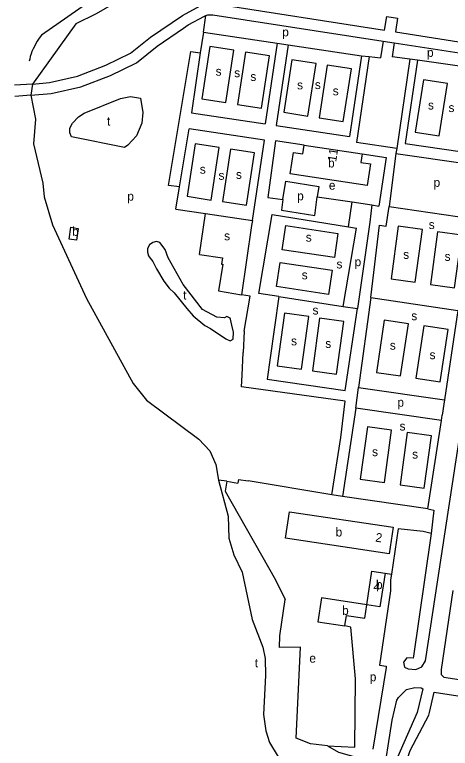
# Model space of a CAD drawing. Extents: x 161093 to 163177, y 379000 to 380904.
# Drawn here: x 161129 to 161325.1, y 380148.5 to 380478.7 of the extents above; entities that cross this region are included whole.
import ezdxf

# ---------------------------------------------------------------- set-up
doc = ezdxf.new("R2010")
doc.units = 0
for name, color, linetype in [('BLT_Basislijn', 7, 'Continuous'), ('BLT_Bebouwing', 7, 'Continuous'), ('BLT_Centroide', 7, 'Continuous'), ('BLT_Huisnummer', 7, 'Continuous'), ('BLT_Vlakafsluiter', 7, 'Continuous')]:
    doc.layers.add(name, color=color, linetype=linetype)

msp = doc.modelspace()

# ---------------------------------------------------------------- linework, layer by layer
at = {"layer": 'BLT_Basislijn'}
for p, q in [((161164.87, 380486.08), (161141.11, 380469.52)), ((161213.97, 380470.87), (161215.05, 380478.25)), ((161213.97, 380470.87), (161212.59, 380461.47)), ((161213.97, 380470.87), (161247.21, 380465.91)), ((161247.21, 380465.91), (161241.82, 380429.61)), ((161252.14, 380465.09), (161246.75, 380428.79)), ((161247.21, 380465.91), (161252.14, 380465.09)), ((161252.14, 380465.09), (161285.1, 380460.17)), ((161294.86, 380466.8), (161293.76, 380459.24)), ((161294.86, 380466.8), (161299.8, 380466.04)), ((161299.8, 380466.04), (161298.88, 380459.75)), ((161299.8, 380466.04), (161333.35, 380460.86)), ((161212.59, 380461.47), (161208.62, 380434.57)), ((161285.1, 380460.17), (161279.71, 380423.86)), ((161288.55, 380459.85), (161282.85, 380421.09)), ((161285.1, 380460.17), (161288.55, 380459.85)), ((161288.55, 380459.85), (161293.76, 380459.24)), ((161306.83, 380458.65), (161298.88, 380459.75)), ((161306.83, 380458.65), (161300.97, 380418.43)), ((161332.45, 380455.09), (161310.37, 380458.16)), ((161137.07, 380447.48), (161129.03, 380446.89)), ((161319.48, 380224.32), (161352.93, 380444.22)), ((161136.28, 380442.39), (161129.11, 380441.88)), ((161136.28, 380442.39), (161138.38, 380431.69)), ((161160.25, 380434.41), (161176.64, 380440.92)), ((161208.62, 380434.57), (161241.82, 380429.61)), ((161246.75, 380428.79), (161279.71, 380423.86)), ((161203.26, 380401.14), (161207.6, 380427.32)), ((161300.97, 380418.43), (161282.85, 380421.09)), ((161300.97, 380418.43), (161300.65, 380416.24)), ((161300.65, 380416.24), (161297.61, 380392.33)), ((161300.65, 380416.24), (161338.09, 380410.75)), ((161201.62, 380391.21), (161203.26, 380401.14)), ((161280.87, 380394.42), (161289.73, 380393.05)), ((161201.62, 380391.21), (161214.99, 380389.19)), ((161289.73, 380393.05), (161292.92, 380392.55)), ((161212.23, 380370.74), (161214.99, 380389.19)), ((161214.99, 380389.19), (161236.01, 380386)), ((161276.92, 380347.43), (161282.88, 380382.65)), ((161279.27, 380383.23), (161282.88, 380382.65)), ((161289.31, 380351.48), (161283.84, 380310.9)), ((161289.31, 380351.48), (161328.55, 380345.63)), ((161276.92, 380347.43), (161283.27, 380346.46)), ((161328.55, 380345.63), (161322.52, 380305.29)), ((161295.41, 380341.22), (161291.82, 380317.68)), ((161313.19, 380338.61), (161309.64, 380315.11)), ((161231.43, 380316.44), (161231.92, 380326.6)), ((161309.64, 380315.11), (161320.54, 380313.53)), ((161282.53, 380301.57), (161283.84, 380310.9)), ((161322.52, 380305.29), (161322.25, 380303.47)), ((161322.25, 380303.47), (161321.44, 380298.45)), ((161314.99, 380256.29), (161321.08, 380296.09)), ((161321.08, 380296.09), (161321.44, 380298.45)), ((161229.79, 380269.57), (161234.13, 380268.9)), ((161271.81, 380262.66), (161234.13, 380268.9)), ((161224.57, 380268.68), (161229.51, 380267.86)), ((161276.56, 380261.87), (161271.81, 380262.66)), ((161314.99, 380256.29), (161276.56, 380261.87)), ((161316.48, 380245.23), (161313.46, 380224.32)), ((161295.83, 380227.34), (161298.65, 380226.92)), ((161298.65, 380226.92), (161298.26, 380224.32)), ((161246.49, 380224.32), (161250.75, 380215.57))]:
    msp.add_line(p, q, dxfattribs=at)
for points in [[(161184.65, 380498.1), (161178.49, 380486.62), (161165.7, 380479.06), (161156.61, 380474.6), (161137.07, 380447.48)], [(161213.84, 380483.12), (161215.09, 380483.55), (161218.52, 380483.64), (161295.56, 380471.7), (161296.49, 380477.82), (161301.35, 380477.09), (161300.47, 380470.93), (161328.98, 380466.5), (161329.9, 380472.69), (161334.48, 380471.98), (161335.13, 380471.86), (161352.54, 380469.32), (161354.21, 380468.64), (161355.48, 380467.36), (161355.94, 380465.82), (161356, 380464.58), (161355.58, 380461.89)], [(161137.07, 380447.48), (161144.71, 380448.17), (161157.32, 380451.01), (161170.13, 380455.89), (161181.11, 380461.31), (161190.23, 380468.57), (161204.57, 380478.35), (161212.5, 380482.66), (161213.84, 380483.12)], [(161204.95, 380472.56), (161207.18, 380474.08), (161214.51, 380478.06), (161215.05, 380478.25)], [(161215.05, 380478.25), (161215.98, 380478.57), (161218.2, 380478.63), (161294.86, 380466.8)], [(161136.28, 380442.39), (161145.49, 380443.22), (161158.76, 380446.21), (161172.13, 380451.3), (161183.8, 380457.06), (161193.2, 380464.55), (161204.95, 380472.56)], [(161141.11, 380469.52), (161140.05, 380468.16), (161139.18, 380466.72), (161138.61, 380465.64), (161137.9, 380464.32), (161137.33, 380463.25), (161136.83, 380462.14), (161136.4, 380461), (161136.06, 380459.84), (161135.79, 380458.66), (161135.63, 380457.76)], [(161216.87, 380464.36), (161213.22, 380440.78), (161224.06, 380439.1), (161227.71, 380462.68), (161216.87, 380464.36)], [(161203.26, 380401.14), (161198.32, 380401.88), (161208.3, 380462.17), (161212.59, 380461.47)], [(161232.91, 380461.81), (161229.26, 380438.22), (161240.1, 380436.55), (161243.75, 380460.13), (161232.91, 380461.81)], [(161253.84, 380458.33), (161250.19, 380434.75), (161261.03, 380433.07), (161264.68, 380456.65), (161253.84, 380458.33)], [(161310.37, 380458.16), (161304.76, 380420.69), (161338.82, 380415.69)], [(161310.37, 380458.16), (161306.83, 380458.65)], [(161269.74, 380455.92), (161266.09, 380432.33), (161276.93, 380430.66), (161280.58, 380454.24), (161269.74, 380455.92)], [(161312.97, 380449.36), (161309.31, 380425.78), (161320.15, 380424.1), (161323.8, 380447.69), (161312.97, 380449.36)], [(161176.64, 380440.92), (161181.15, 380441.89), (161185.62, 380441.13), (161186.65, 380434.59), (161186.33, 380429.93), (161183.86, 380424.16), (161179.94, 380420.01), (161178.45, 380418.98), (161154.54, 380423.68), (161153.86, 380425.44), (161153.86, 380427.63), (161155.11, 380429.82), (161157.71, 380432.68), (161160.25, 380434.41)], [(161138.38, 380431.69), (161137.56, 380420.54), (161141.7, 380402.83), (161142.3, 380396.73), (161146.06, 380384.11), (161161.38, 380350.9), (161182.43, 380312.66), (161188.42, 380305.19), (161211.96, 380287.61), (161216.94, 380282.42), (161219.64, 380276.21), (161220.85, 380269.22)], [(161236.01, 380386), (161241.49, 380422.18), (161207.6, 380427.32)], [(161259.33, 380419.95), (161246.45, 380421.9), (161242.93, 380396.36), (161249.74, 380395.45)], [(161210.3, 380420.54), (161206.64, 380396.96), (161217.48, 380395.28), (161221.13, 380418.86), (161210.3, 380420.54)], [(161226.2, 380418.2), (161222.54, 380394.62), (161233.38, 380392.94), (161237.03, 380416.52), (161226.2, 380418.2)], [(161285.47, 380416.02), (161296.22, 380414.37), (161292.92, 380392.55)], [(161249.74, 380395.45), (161251.02, 380403.74), (161265.9, 380401.35), (161265.2, 380396.75)], [(161249.74, 380395.45), (161249.42, 380393.07), (161249.07, 380390.76), (161264.06, 380388.38), (161264.4, 380390.7), (161265.2, 380396.75)], [(161265.2, 380396.75), (161280.87, 380394.42)], [(161279.27, 380383.23), (161280.87, 380394.42)], [(161289.73, 380393.05), (161288.85, 380385.33), (161283.27, 380346.46)], [(161289.31, 380351.48), (161293.3, 380383.97), (161296.23, 380383.56), (161297.61, 380392.33)], [(161297.61, 380392.33), (161334.56, 380386.89)], [(161247.99, 380351.85), (161239, 380353.24), (161244.9, 380388.8), (161279.27, 380383.23)], [(161236.01, 380386), (161235.7, 380383.77), (161231.15, 380352.64)], [(161251.11, 380383.75), (161274.55, 380380.22), (161272.92, 380369.38), (161249.47, 380372.9), (161251.11, 380383.75)], [(161301.66, 380383.52), (161298.42, 380359.87), (161309.29, 380358.38), (161312.53, 380382.03), (161301.66, 380383.52)], [(161319.38, 380380.94), (161316.14, 380357.3), (161327, 380355.81), (161330.24, 380379.45), (161319.38, 380380.94)], [(161212.23, 380370.74), (161222.58, 380369.24), (161222.15, 380366.47), (161222.71, 380366.38), (161220.81, 380354.34), (161231.15, 380352.64)], [(161248.5, 380367.17), (161271.94, 380363.64), (161270.31, 380352.8), (161246.87, 380356.32), (161248.5, 380367.17)], [(161232.38, 380336.33), (161235.02, 380352), (161231.15, 380352.64)], [(161247.99, 380351.85), (161244.02, 380324.3), (161242.65, 380314.65)], [(161247.99, 380351.85), (161276.92, 380347.43)], [(161242.65, 380314.65), (161277.86, 380309.62), (161283.27, 380346.46)], [(161250.49, 380344.36), (161247.25, 380320.71), (161258.12, 380319.22), (161261.36, 380342.87), (161250.49, 380344.36)], [(161266.29, 380342.04), (161263.05, 380318.39), (161273.92, 380316.9), (161277.16, 380340.55), (161266.29, 380342.04)], [(161291.82, 380317.68), (161302.74, 380316.11), (161306.32, 380339.62), (161295.41, 380341.22)], [(161320.54, 380313.53), (161324.1, 380337.03), (161313.19, 380338.61)], [(161232.38, 380336.33), (161231.92, 380326.6)], [(161231.16, 380311.14), (161231.43, 380316.44)], [(161271.81, 380262.66), (161275.84, 380288.37), (161277.77, 380304.68), (161231.16, 380311.14)], [(161283.84, 380310.9), (161322.52, 380305.29)], [(161282.53, 380301.57), (161276.56, 380261.87)], [(161321.08, 380296.09), (161282.53, 380301.57)], [(161287.84, 380293.26), (161284.6, 380269.62), (161295.46, 380268.13), (161298.7, 380291.77), (161287.84, 380293.26)], [(161305.76, 380290.7), (161302.52, 380267.06), (161313.38, 380265.57), (161316.62, 380289.21), (161305.76, 380290.7)], [(161220.85, 380269.22), (161225.11, 380253.05), (161225.4, 380243.06)], [(161229.79, 380269.57), (161229.51, 380267.86)], [(161224.57, 380268.68), (161223.84, 380264.27), (161246.49, 380224.32)], [(161314.99, 380256.29), (161317.7, 380255.64), (161316.48, 380245.23)], [(161316.48, 380245.23), (161312.96, 380246.05), (161301.69, 380247.32), (161298.65, 380226.92)], [(161225.4, 380243.06), (161227.67, 380235.59), (161231.49, 380227.73), (161235.88, 380206.53), (161240.79, 380193.99), (161241.73, 380188.94), (161241.93, 380181.27), (161241.02, 380163.69), (161242.04, 380156.47), (161243.72, 380151.15), (161247.7, 380144.74)], [(161298.26, 380224.32), (161298.18, 380219.44), (161293.21, 380186), (161296.19, 380185.57), (161296.27, 380184.85), (161290.29, 380148.22)], [(161313.46, 380224.32), (161308.51, 380189.99), (161308.32, 380189.17), (161305.55, 380189.2), (161304.05, 380187.29), (161304.56, 380185.04), (161306.17, 380184.29), (161309.62, 380183.97), (161312.27, 380185.22), (161313.92, 380187.83), (161319.48, 380224.32)], [(161326.24, 380219.49), (161320.93, 380184.07), (161320.96, 380181.79), (161322.14, 380180.53), (161384, 380171.06), (161385.05, 380170.9)], [(161257.64, 380194.04), (161248.24, 380193.93), (161248.31, 380199.15), (161250.75, 380215.57)], [(161269.88, 380149.64), (161282.17, 380149.06), (161282.5, 380179.86), (161280.41, 380203.1), (161277.65, 380203.6)], [(161269.88, 380149.64), (161262.16, 380150.59), (161255.78, 380153.11), (161257.64, 380194.04)], [(161294.65, 380133.35), (161298.9, 380161.26), (161301.02, 380170.18), (161301.82, 380171.41), (161305.42, 380174.93), (161309.08, 380175.9), (161312.06, 380175.79), (161312.69, 380175.36), (161310.26, 380164.67), (161299.91, 380141.03)], [(161315.69, 380164.58), (161317.84, 380173.75), (161342.15, 380170.09)], [(161305.97, 380120.42), (161304.44, 380133.57), (161304.88, 380139.67), (161305.64, 380143.48), (161307.07, 380147.62), (161315.45, 380163.46), (161315.69, 380164.58)], [(161269.88, 380149.64), (161274.8, 380146.75), (161289.14, 380142.69)]]:
    msp.add_lwpolyline(points, dxfattribs=at)
msp.add_lwpolyline([(161194.41, 380376.18), (161192.8, 380376.57), (161191.22, 380376.18), (161189.72, 380375.15), (161188.86, 380373.4), (161188.76, 380371.75), (161189.3, 380370.17), (161189.97, 380369.04), (161191.19, 380367.63), (161192.87, 380364.24), (161196.22, 380358.71), (161198.52, 380355.67), (161200.85, 380353.56), (161206.47, 380346.41), (161209.4, 380343.12), (161214.65, 380338.77), (161217.18, 380337.42), (161224.12, 380332.75), (161226.02, 380331.96), (161227.38, 380332.73), (161227.6, 380335.85), (161226.71, 380338.91), (161226.13, 380341.69), (161226.04, 380342.15), (161224.46, 380342.8), (161223.51, 380342.22), (161220, 380342.6), (161213.55, 380346.02), (161204.91, 380357.21), (161198.15, 380369.22), (161196.81, 380372.96)], close=True, dxfattribs=at)
at = {"layer": 'BLT_Bebouwing'}
for p, q in [((161259.33, 380419.95), (161285.47, 380416.02)), ((161250.88, 380243.13), (161252.66, 380255))]:
    msp.add_line(p, q, dxfattribs=at)
for points in [[(161285.47, 380416.02), (161284.9, 380412.15), (161289.19, 380411.51), (161287.73, 380401.81), (161253, 380407.01), (161254.46, 380416.7), (161258.75, 380416.06), (161259.33, 380419.95)], [(161157.66, 380382.48), (161156.85, 380377.18), (161153.53, 380377.69), (161154.34, 380382.99), (161157.66, 380382.48)], [(161252.66, 380255), (161299.37, 380248.01), (161297.62, 380236.12), (161250.88, 380243.13)], [(161287.5, 380213.12), (161289.77, 380228.25), (161295.83, 380227.34)], [(161295.83, 380227.34), (161293.45, 380212.24), (161287.5, 380213.12)], [(161287.5, 380213.12), (161267.19, 380216.23), (161265.54, 380205.45), (161277.65, 380203.6)], [(161277.65, 380203.6), (161278.36, 380208.3), (161286.57, 380207.05), (161287.5, 380213.12)]]:
    msp.add_lwpolyline(points, dxfattribs=at)
at = {"layer": 'BLT_Vlakafsluiter'}
for p, q in [((161137.07, 380447.48), (161136.28, 380442.39)), ((161224.57, 380268.68), (161220.85, 380269.22))]:
    msp.add_line(p, q, dxfattribs=at)

# ---------------------------------------------------------------- texts
at = {"layer": 'BLT_Centroide'}
for s, p in [('p', (161249.45, 380468.91)), ('p', (161314.61, 380459.69)), ('s', (161219.47, 380451.22)), ('s', (161227.82, 380450.53)), ('s', (161235.11, 380448.86)), ('s', (161256.16, 380445.07)), ('s', (161264.15, 380445.21)), ('s', (161272.2, 380442.39)), ('s', (161315.06, 380436)), ('s', (161324.3, 380434.86)), ('t', (161170.57, 380428.8)), ('b', (161270.09, 380409.93)), ('s', (161212.36, 380407.13)), ('s', (161228.63, 380404.77)), ('s', (161220.78, 380404.38)), ('p', (161317.57, 380401.21)), ('e', (161270.45, 380399.92)), ('p', (161179.72, 380394.98)), ('p', (161256.18, 380395.15)), ('s', (161315.41, 380382.22)), ('b', (161154.88, 380379.18)), ('s', (161223.32, 380377.15)), ('s', (161260.06, 380376.54)), ('s', (161303.88, 380368.8)), ('p', (161282.03, 380365.49)), ('s', (161322.55, 380367.9)), ('s', (161273.87, 380364.49)), ('s', (161258.22, 380359.59)), ('t', (161204.84, 380350.5)), ('s', (161263.09, 380343.75)), ('s', (161307.56, 380341.17)), ('s', (161253.44, 380329.86)), ('s', (161268.83, 380328.71)), ('s', (161297.89, 380327.91)), ('s', (161315.76, 380323.65)), ('p', (161301.29, 380302.27)), ('s', (161302.27, 380291.53)), ('s', (161289.89, 380280.01)), ('s', (161307.93, 380278.91)), ('b', (161273.48, 380243.86)), ('b', (161291.67, 380220.23)), ('b', (161276.41, 380208.59)), ('e', (161261.68, 380187.1)), ('t', (161237.13, 380184.97)), ('p', (161288.87, 380178.7))]:
    msp.add_text(s, height=4, dxfattribs=at).set_placement(p)
at = {"layer": 'BLT_Huisnummer'}
for s, rotation, p in [('11', 81.1075, (161273.72, 380412.31)), ('2', 351.4205, (161291.2, 380241.6)), ('4', 351.6541, (161290.27, 380219.48))]:
    msp.add_text(s, height=4, rotation=rotation, dxfattribs=at).set_placement(p)

doc.saveas('drawing.dxf')
